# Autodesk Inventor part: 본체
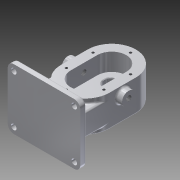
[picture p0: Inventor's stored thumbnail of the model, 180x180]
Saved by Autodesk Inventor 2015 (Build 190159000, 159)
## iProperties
Created: 2020-09
Part Number: 본체
Material: 알루미늄 6061
Document SubType Name: Modeling
Designer: Administrator
Density: 2.7 g/cm^3
Appearance: 알루미늄 - 평지
Mass: 1440.38 g
Surface Area: 785.389 cm^2
Volume: 533.473 cm^3
Author: Administrator
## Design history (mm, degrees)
sketch "스케치1"
  geometry: L1 (0, 0)-(0, 44); L2 (-40, 0)-(-40, 44); L3 (40, 44)-(40, 0); A1 r 40 centre (0, 0) between (-40, 0) and (40, 0); A2 r 40 centre (0, 44) between (40, 44) and (-40, 44); 1 further point
  constraints: 8 end point, 4 point on circle, 4 tangent, 2 centre point, 1 midpoint, 1 parallel, 1 vertical
  dimensions: "d10" = 44 distance of L1.start L1.end; "d11" = 40 radius of A2
extrude "돌출1" new body sketch "스케치1" distance "d12" = 53; taper "d13" = 0 deg
sketch "스케치2"
  geometry: L1 (0, 44)-(0, 0); L2 (24, 44)-(24, 0); L3 (-24, 0)-(-24, 44); A1 r 40 centre (0, 44) between (40, 44) and (-40, 44) reference; A2 r 40 centre (0, 0) between (-40, 0) and (40, 0) reference; A3 r 24 centre (0, 44) between (24, 44) and (-24, 44); A4 r 24 centre (0, 0) between (-24, 0) and (24, 0); 2 further points
  constraints: 8 end point, 4 point on circle, 4 tangent, 2 centre point, 1 midpoint, 1 parallel, 1 vertical
  dimensions: "d14" = 24 radius of A4
extrude "돌출2" cut sketch "스케치2" distance "d15" = 29; taper "d16" = 0 deg
sketch "스케치4"
  geometry: L1 (0, 44)-(0, 0); L2 (31, 44)-(31, 0); L3 (-31, 0)-(-31, 44); L4 (0, 44)-(-31, 44); L5 (0, 44)-(31, 44); L6 (0, 0)-(0, -31); L7 (0, 0)-(31, 0); L8 (0, 0)-(-31, 0); A1 r 40 centre (0, 44) between (40, 44) and (-40, 44) reference; A2 r 40 centre (0, 0) between (-40, 0) and (40, 0) reference; A3 r 31 centre (0, 44) between (31, 44) and (-31, 44); A4 r 31 centre (0, 0) between (-31, 0) and (31, 0); A5 r 24 centre (0, 44) between (24, 44) and (-24, 44) reference; 8 further points
  constraints: 18 end point, 6 point on circle, 5 coincident, 4 horizontal, 4 tangent, 2 centre point, 1 midpoint, 1 parallel, 1 vertical
  dimensions: "d17" = 31 radius of A4
hole "구멍1" sketch "스케치4" at (0, 75), (-31, 44), (31, 44), (-31, 0), (0, -31), (31, 0) diameter "d18" = 4.134; stored, may be unused: countersink angle "d22" = 82 deg, drill point angle "d24" = 118 deg; dims "d19" = 10, "d20" = 3.023, "d21" = 2, "d23" = 12
sketch "스케치7"
  geometry: C1 r 12.5 at (0, 44); C2 r 12.5 at (0, 0); A1 r 40 centre (0, 44) between (40, 44) and (-40, 44) reference; A2 r 40 centre (0, 0) between (-40, 0) and (40, 0) reference; 1 further point
  constraints: 2 centre point, 2 coincident
  dimensions: "d25" = 25 diameter of C1; "d26" = 25 diameter of C2
extrude "돌출3" cut sketch "스케치7" distance "d27" = 15; taper "d28" = 0 deg
sketch "스케치11"
  geometry: L1 (24, 44)-(24, 0) reference; L2 (-24, 0)-(-24, 44) reference; L3 (-40, 44)-(-40, 0) reference; L4 (40, 0)-(40, 44) reference; C1 r 2.067 at (0, -31) reference; C2 r 2.067 at (31, 44) reference; C3 r 2.067 at (0, 75) reference; C4 r 2.067 at (-31, 44) reference; C5 r 2.067 at (-31, 0) reference; C6 r 2.067 at (31, 0) reference; C7 r 8.5 at (0, 44); A1 r 24 centre (0, 44) between (24, 44) and (-24, 44) reference; A2 r 24 centre (0, 0) between (-24, 0) and (24, 0) reference; A3 r 40 centre (0, 0) between (-40, 0) and (40, 0) reference; A4 r 40 centre (0, 44) between (40, 44) and (-40, 44) reference; 1 further point
  constraints: 1 centre point, 1 coincident
  dimensions: "d34" = 17 diameter of C7
extrude "돌출5" cut sketch "스케치11" distance "d35" = 34.75; taper "d36" = 0 deg
sketch "스케치12"
  geometry: L1 (40, 0)-(40, 44) reference; L2 (-40, 44)-(-40, 0) reference; C1 r 8.5 at (0, 44) reference; C2 r 19 at (0, 44); A1 r 40 centre (0, 44) between (40, 44) and (-40, 44) reference; A2 r 40 centre (0, 0) between (-40, 0) and (40, 0) reference; 1 further point
  constraints: 1 centre point, 1 coincident
  dimensions: "d37" = 38 diameter of C2
extrude "돌출6" join sketch "스케치12" distance "d38" = 17; taper "d39" = 0 deg
sketch "스케치13"
  geometry: L1 (40, -44)-(40, 0) reference; L2 (-40, 0)-(-40, -44) reference; C1 r 19 at (0, 0) reference; C2 r 14 at (0, 0); A1 r 40 centre (0, 0) between (40, 0) and (-40, 0) reference; A2 r 40 centre (0, -44) between (-40, -44) and (40, -44) reference; 1 further point
  constraints: 1 centre point, 1 coincident
  dimensions: "d40" = 28 diameter of C2
extrude "돌출7" cut sketch "스케치13" distance "d41" = 7.3; taper "d42" = 0 deg
sketch "스케치14"
  geometry: L1 (0, 44)-(0, 0) reference; L2 (0, 44)-(-53, 44) reference; L3 (-53, 0)-(-53, 44) reference; L4 (0, 0)-(-53, 0) reference; L5 (-53, 44)-(-53, 0) reference; L6 (-53, 22)-(-39, 22); C1 r 11 at (-39, 22); 1 further point
  constraints: 2 end point, 1 centre point, 1 coincident, 1 horizontal, 1 midpoint
  dimensions: "d43" = 14 distance of L6.start L6.end; "d44" = 22 diameter of C1
extrude "돌출8" join sketch "스케치14" distance "d45" = 10; taper "d46" = 0 deg
node "스케치15"
sketch "스케치16"
  geometry: L1 (0, 0)-(0, 44) reference; L2 (0, 0)-(53, 0) reference; L3 (53, 44)-(53, 0) reference; L4 (0, 44)-(53, 44) reference; L5 (53, 44)-(53, 0) reference; L6 (53, 22)-(39, 22); C1 r 11 at (39, 22); 1 further point
  constraints: 2 end point, 1 centre point, 1 coincident, 1 horizontal, 1 midpoint
  dimensions: "d47" = 14 distance of L6.start L6.end; "d48" = 22 diameter of C1
extrude "돌출9" join sketch "스케치16" distance "d49" = 10; taper "d50" = 0 deg
sketch "스케치17"
  geometry: C1 r 11 at (0, 0) reference; 2 further points
  constraints: 1 coincident
hole "구멍2" sketch "스케치17" at (0, 0) diameter "d51" = 8.376; stored, may be unused: countersink angle "d55" = 90 deg, drill point angle "d57" = 118 deg; dims "d52" = 20, "d53" = 4, "d54" = 2, "d56" = 27.3
node "작업 평면2"
  node "작업 평면1"
sketch "스케치18"
  geometry: L1 (16, -53)-(-64, -53) reference; L2 (16, -53)-(16, 0) reference; L3 (-64, 0)-(16, 0) reference; L4 (-64, -53)-(-64, 0) reference; L5 (26, -70)-(-74, -70); L6 (-84, -60)-(-84, 20); L7 (-74, 30)-(26, 30); L8 (36, 20)-(36, -60); L9 (-43, -70)-(-5, -70) reference; A1 r 10 centre (-74, 20) between (-74, 30) and (-84, 20); A2 r 10 centre (26, 20) between (36, 20) and (26, 30); A3 r 10 centre (26, -60) between (26, -70) and (36, -60); A4 r 10 centre (-74, -60) between (-84, -60) and (-74, -70); 1 further point
  constraints: 10 tangent, 8 end point, 8 point on circle, 4 centre point, 3 equal radius, 2 midpoint, 2 parallel, 1 horizontal, 1 perpendicular
  dimensions: "d61" = 10 radius of A1; "d64" = 30 distance between parallel lines of L3 L7
extrude "돌출10" join sketch "스케치18" distance "d65" = 10; taper "d66" = 0 deg
fillet "모깎기1" dims "d67" = 3
sketch "스케치19"
  geometry: L1 (84, -20)-(84, 60) reference; L2 (-26, -30)-(74, -30) reference; L3 (-36, 60)-(-36, -20) reference; L4 (74, 70)-(-26, 70) reference; C1 r 4.5 at (-26, -20); C2 r 4.5 at (-26, 60); C3 r 4.5 at (74, 60); C4 r 4.5 at (74, -20); A1 r 10 centre (74, -20) between (74, -30) and (84, -20) reference; A2 r 10 centre (-26, -20) between (-36, -20) and (-26, -30) reference; A3 r 10 centre (-26, 60) between (-26, 70) and (-36, 60) reference; A4 r 10 centre (74, 60) between (84, 60) and (74, 70) reference; 1 further point
  constraints: 4 centre point, 4 coincident
  dimensions: "d68" = 9 diameter of C1; "d69" = 9 diameter of C2; "d70" = 9 diameter of C3; "d71" = 9 diameter of C4
extrude "돌출11" cut sketch "스케치19" distance "d72" = 10; taper "d73" = 0 deg
node "작업 평면3"
sketch "스케치20"
  geometry: L1 (10, 68)-(10, 10); L2 (0, 10)-(100, 10) reference; L3 (90, 68)-(90, 10); L4 (10, 10)-(90, 10); A1 r 40 centre (50, 68) between (10, 68) and (90, 68); 1 further point
  constraints: 6 end point, 2 point on circle, 2 point on line, 1 centre point, 1 collinear, 1 perpendicular, 1 vertical
  dimensions: "d75" = 40 radius of A1
extrude "돌출12" join sketch "스케치20" distance "d76" = 37; taper "d77" = 0 deg
sketch "스케치21"
  geometry: A1 r 10 centre (-26, -20) between (-36, -20) and (-26, -30) reference; 2 further points
  constraints: 1 other
  dimensions: "d78" = 12 vertical distance of A1.end point (24, -18); "d79" = 60 horizontal distance of A1.start point (24, -18)
feature "엠보싱1" sketch "스케치21" dims "d10" = 44, "d11" = 40, "d80" = 0.5, "d81" = 0
fillet "모깎기2" dims "d82" = 3
fillet "모깎기3" dims "d83" = 3
chamfer "모따기1" distance "d84" = 1; stored, may be unused: second distance "d85" = 2, angle "d86" = 45 deg
fillet "모깎기4" dims "d87" = 0.5
node "솔리드1"
node "투영된 루프2"
node "투영된 루프3"
node "투영된 루프4"
node "투영된 루프5"
node "투영된 루프6"
node "투영된 루프7"
node "투영된 루프8"
node "투영된 루프9"
other parameters: "d74" = -62
